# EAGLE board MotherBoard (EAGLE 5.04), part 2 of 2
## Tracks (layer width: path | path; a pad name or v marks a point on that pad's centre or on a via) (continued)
N$125 (continued)
  Bottom 1.016: Q3.3 288.77,206.69 arc90 286.23,204.15 286.23,201.61 arc-90 283.69,199.07 277.34,199.07 arc90 DSP1.6
N$126
  Bottom 1.016: DSP1.8 272.26,212.57 arc-90 274.8,215.11 278.61,215.11 arc-90 281.15,212.57 281.15,207.96 arc-90 Q2.3
N$127
  Bottom 1.016: Q5.3 DSP1.9
N$128
  Bottom 1.016: Q4.3 261.01,211.96 arc-45 DSP1.12
N$129
  Bottom 1.016: R105.1 R102.1 183.36,167.32 arc90 IC11.2
N$130
  Bottom 1.016: D3.C 182.74,157.81 arc-45 D4.A
N$131
  Bottom 1.016: Q1.2 IC6.2
N$132
  Bottom 1.016: Q1.1 149.59,54.29 arc-90 147.8,56.09 IC6.1
N$133
  Bottom 1.016: Q14.2 R122.2 13.18,17.57 arc-90 14.97,19.37 C58.2
N$134
  Bottom 1.016: LED16.A R124.2
N$135
  Bottom 1.016: Q14.3 R124.1
N$136
  Bottom 1.016: LED16.K arc90 14.13,3.81 40.66,3.81 arc90 43.66,6.81 LED17.A
N$137
  Bottom 1.016: R110.1 JP13.1 IC12.2
N$138
  Bottom 1.016: LED3.K R17.1
N$139
  Bottom 1.016: LED5.K R19.1
N$140
  Bottom 1.016: LED6.K R20.1
N$141
  Bottom 0.813: R21.1 LED7.K
N$142
  Bottom 0.813: R22.1 LED8.K
N$143
  Bottom 0.813: R23.1 LED9.K
N$144
  Bottom 0.813: R24.1 LED10.K
N$145
  Bottom 1.016: LED4.K R18.1
N$146
  Bottom 1.016: R99.2 R100.S
N$147
  Bottom 1.016: R106.2 R107.S
N$148
  Bottom 1.016: R99.1 C37.2 JP11.2
N$149
  Bottom 1.016: JP12.2 C39.2 R106.1
N$150
  Bottom 1.016: C70.1 R155.1 R154.2
N$151
  Bottom 1.016: PH1.1 136.37,160.97 R112.1 R111.1
N$152
  Bottom 1.016: 203.04,165.77 S39.2 | S39.1 199.87,165.77 | 199.87,165.77 203.04,165.77 | 203.04,165.77 203.04,165.74 | 199.87,165.77 199.87,167.64 arc90 R104.1
N$153
  Bottom 1.016: 203.04,174.66 S40.2 | S40.1 199.87,174.66 | 199.87,174.66 203.04,174.66 | 203.04,174.66 203.04,174.62 | 199.87,174.66 199.87,176.53 arc90 R108.1
N$154
  Bottom 1.016: S41.1 196.65,183.55 196.69,183.52 196.73,183.55 199.87,183.55 | 199.87,183.55 S41.2 | 199.87,183.55 199.87,186.05 arc90 R109.1
N$155
  Bottom 1.422: C51.1 TR1.3 58.9,4.76 SPK.2
N$156
  Bottom 1.016: S38.1 196.69,156.88 | 196.69,156.88 199.87,156.88 | 199.87,156.88 S38.2 | 196.69,156.88 196.69,156.84 | 199.87,156.88 199.87,158.75 arc90 R103.1
N$157
  Bottom 1.016: R119.1 JP16.2
N$158
  Bottom 1.016: R116.2 R113.1 R115.1
N$159
  Bottom 1.016: TR1.2 R119.2
N$160
  Bottom 1.016: R117.2 117.32,147.75 arc45 C49.1 | R117.2 108.69,136.21 arc-45 D5.A JP15.3 104.12,139.38 arc-90 99.54,143.96 C48.2 | IC13.2 126.84,142.56 arc90 123.67,139.38 arc-90 120.49,136.21 R117.2
N$161
  Top 1.27: IC13.1 126.4,140.02 arc-45 124.98,140.61 123.74,141.85 arc-45 122.4,145.09 R118.A
  Bottom 1.016: R117.1 IC13.1
N$162
  Bottom 1.016: IC8.7 R57.2
N$163
  Bottom 1.016: IC8.6 R58.2
N$164
  Bottom 1.016: IC8.4 R60.2
N$165
  Bottom 1.016: IC8.3 R61.2
N$166
  Bottom 1.016: IC8.2 R62.2
N$167
  Bottom 1.016: IC8.1 R63.2
N$168
  Bottom 1.016: R64.2 IC8.15
N$169
  Bottom 1.016: IC8.5 R59.2
N$170
  Bottom 1.016: R50.2 IC7.6
N$171
  Bottom 1.016: R52.2 IC7.4
N$172
  Bottom 1.016: R53.2 IC7.3
N$173
  Bottom 1.016: R54.2 IC7.2
N$174
  Bottom 1.016: R55.2 IC7.1
N$175
  Bottom 1.27: IC7.15 R56.2
N$176
  Bottom 1.016: R51.2 IC7.5
N$177
  Bottom 1.016: R49.1 291.31,25.96 arc45 290.13,28.8 289.94,28.99 arc-45 288.77,31.83 M1.13
N$178
  Bottom 1.016: R47.2 Q6.2
N$179
  Bottom 1.016: R48.2 Q7.2
N$180
  Bottom 1.016: R65.2 Q8.2
N$181
  Bottom 1.016: R66.2 Q9.2
N$182
  Bottom 1.016: R67.2 Q10.2
N$183
  Bottom 1.016: R68.2 Q11.2
N$184
  Bottom 1.016: R69.2 Q12.2
N$185
  Bottom 1.016: R70.2 Q13.2
N$186
  Bottom 1.778: TR2.1 P2.1
N$187
  Bottom 1.016: LED20.K R136.2
N$188
  Bottom 1.778: P1.1 RE1.1
N$189
  Bottom 1.676: B1.AC1 3.02,203.63 arc-45 SW1.2
N$190
  Bottom 1.016: R140.2 RE1.4 arc90 354.81,50.48 354.81,56.83 arc90 JP19.1
N$191
  Bottom 1.016: JP20.1 325.6,6.56 arc90 327.39,4.76 331.42,4.76 arc90 333.22,6.56 TR2.3
N$192
  Bottom 1.93: 9.45,210.11 11.68,207.87 arc45 13.75,207.01 PWR.+ | 9.45,210.11 PWR.C | SW1.P 5.99,211.77 arc-45 9.04,210.51 9.45,210.11
N$193
  Bottom 1.016: M1.3 R50.1
N$194
  Bottom 1.016: M1.4 R51.1
N$195
  Bottom 1.016: R52.1 M1.10
N$196
  Bottom 1.016: M1.6 R53.1
N$197
  Bottom 1.016: R54.1 M1.11
N$198
  Bottom 1.016: R55.1 M1.15
N$199
  Bottom 1.016: M1.16 281.15,39.94 arc-90 283.44,42.23 R56.1
N$200
  Bottom 1.016: R57.1 M2.13
N$201
  Bottom 1.016: M2.3 253.21,30.91 arc-90 255,32.7 R58.1
N$202
  Bottom 1.016: M2.4 R59.1
N$203
  Bottom 1.016: R60.1 M2.10
N$204
  Bottom 1.016: M2.6 260.83,15.29 arc45 259.29,19 arc-45 258.29,21.43 R61.1
N$205
  Bottom 1.016: R62.1 M2.11
N$206
  Bottom 1.016: R63.1 M2.15
N$207
  Bottom 1.016: R64.1 227.49,38.02 arc-90 232.34,42.86 244.32,42.86 arc-90 M2.16
N$208
  Bottom 1.016: R80.1 R88.2 46.2,180.81 arc45 44.73,184.34 44.24,184.83 arc-45 43.66,186.25 R89.1
N$209
  Bottom 1.016: R81.1 R89.2 43.66,180.81 arc45 42.19,184.34 41.7,184.83 arc-45 41.12,186.25 R90.1
N$210
  Bottom 1.016: R82.1 R90.2 41.12,180.81 arc45 39.65,184.34 39.16,184.83 arc-45 38.58,186.25 R91.1
N$211
  Bottom 1.016: R83.1 R91.2 38.58,180.81 arc45 37.11,184.34 36.62,184.83 arc-45 36.04,186.25 R92.1
N$212
  Bottom 1.016: R84.1 R92.2 36.04,180.81 arc45 34.57,184.34 34.08,184.83 arc-45 33.5,186.25 R93.1
N$213
  Bottom 1.016: R85.1 R93.2 33.5,180.81 arc45 32.03,184.34 31.54,184.83 arc-45 30.96,186.25 R94.1
N$214
  Bottom 1.016: R86.1 R94.2 30.96,180.81 arc45 29.49,184.34 29,184.83 arc-45 28.42,186.25 R95.1
N$215
  Top 1.016: IC10.3 12.12,173.67 arc-90 15.72,170.08 15.72,167.1 arc90 19.31,163.51 21.3,163.51 arc90 25.88,168.09 25.88,173.67 arc-90 R87.1
  Bottom 1.016: R87.1 R95.2 | C35.2 IC10.3
N$216
  Bottom 1.016: S37.1 R80.2
N$217
  Bottom 1.016: S37.2 R81.2
N$218
  Bottom 1.016: S37.3 R82.2
N$219
  Bottom 1.016: S37.4 R83.2
N$220
  Bottom 1.016: S37.5 R84.2
N$221
  Bottom 1.016: S37.6 R85.2
N$222
  Bottom 1.016: S37.7 R86.2
N$223
  Bottom 1.016: S37.8 R87.2
N$224
  Bottom 1.016: LDAC.2 4.29,176.21
  Bottom 1.422: R96.2 arc-45 11.91,179.76 IC10.1 IC10.2 4.29,176.21
N$225
  Bottom 1.016: R97.2 18.78,168.59 arc-90 16.99,170.39 16.99,171.13 | 16.99,171.13 16.99,179.5 arc-90 18.78,181.29 R96.1 | 16.99,171.13 IC10.5
N$226
  Bottom 1.016: IC10.6 LED15.K 23.34,169.23 arc-90 R98.2
N$227
  Bottom 1.016: IC10.7 LED15.A
N$228
  Bottom 1.27: 58.87,213.04 58.87,213.02 58.37,212.52 arc45 57.63,210.72 IC9.6 | 58.87,213.04 RS485.2 | 58.87,213.04 R71.2
N$229
  Top 0.406: 169.39,175.58 169.39,176.21 166.85,176.21 166.85,175.58
N$230
  Bottom 0.61: JP10.1 | LED12.A
  Bottom 1.016: LED11.A 66.2,182.56 | 66.2,182.56 LED12.A 66.04,187.64 | 66.2,182.56 LED13.A | 66.04,187.64 JP10.1 | 66.04,187.64 LED14.A
N$231
  Bottom 1.422: PDAC.1 arc90 6.85,147 C71.1 R155.2
N$232
  Bottom 1.016: R154.1 19,147 arc90 20.8,148.8 JP25.2
N$233
  Bottom 1.016: 56.36,202.88 IC9.2 | 56.36,202.88 IC9.3 | S36.3 56.36,202.88
N$234
  Bottom 1.016: S36.2 58.9,199.82 arc-45 59.27,200.71 59.79,201.24 arc45 60.17,202.14 IC9.4
N$235
  Bottom 1.016: S36.4 53.82,199.82 arc45 53.44,200.71 52.92,201.24 arc-45 52.55,202.14 IC9.1
N$236
  Bottom 1.016: C45.2 R114.E
N$237
  Top 0.406: 156.69,175.58 156.69,176.21 159.23,176.21 159.23,175.58
N$238
  Bottom 1.016: R143.2 127.48,35.99 arc90 125.68,37.78 R145.2 arc45 124.3,36.25 Q15.1
N$239
  Bottom 1.016: R141.2 LED21.K
N$240
  Bottom 1.016: R141.1 123.67,31.43 | 123.67,31.43 D6.A arc-90 121.76,32.7 Q15.2 | Q15.2 | 123.67,31.43 K1.16
N$241
  Bottom 1.016: 117.32,6.03 QR1.2
  Bottom 2.184: K1.S1 116.05,9.1 arc45 117.32,6.03
  Bottom 2.54: 117.32,6.03 117.34,6.01
N$242
  Bottom 1.016: R144.2 142.72,35.99 arc90 140.92,37.78 R146.2 140.13,37.74 arc45 139.54,36.32 Q16.1
N$243
  Bottom 1.016: R142.2 LED22.K
N$244
  Bottom 1.016: 138.91,31.43 D7.A arc-90 137,32.7 Q16.2 | 138.91,31.43 R142.1 | 138.91,31.43 K2.16
N$245
  Bottom 1.016: 132.58,6.01 132.56,6.03 QR2.2
  Bottom 2.54: K2.S1 131.29,9.1 arc45 132.56,6.03
N$246
  Bottom 1.016: Q18.2 75.56,26.35 arc-90 72.87,29.05 R153.1 72.87,31.82 arc-90 76.29,35.24 OK2.5
N$247
  Bottom 1.676: Q17.1 89.53,26.35 arc-90 86.84,29.05 R157.2 86.84,32.7 R158.2
N$248
  Bottom 1.016: OK2.1 R156.2
N$249
  Bottom 1.016: 84.3,7.3 M.1 | 86.84,23.81 85.32,23.81 arc-90 83.03,26.1 LED23.K
  Bottom 1.676: Q17.2 86.84,23.81 D10.C | 84.3,7.3 84.3,10.59 arc-45 C69.1 arc45 86.84,16.72 D10.C | D10.C D9.A
N$250
  Bottom 1.016: LED23.A 80.49,24.45 arc90 R151.1
N$251
  Bottom 1.016: R152.1 OK2.6
N$252
  Bottom 1.016: Q18.3 R157.1 77.65,30.16 arc90 80.49,33 R159.2
N$253
  Bottom 1.016: 220V.1 R147.1
N$254
  Bottom 1.016: QR1.1 122.4,6.67 122.37,6.06 QR1.1
  Bottom 2.184: K1.P2 120.02,21.27 | 120.02,21.27 K1.P1 | 120.02,21.27 120.02,10.99 arc45 120.94,8.76 121.84,7.85 arc-45 122.37,6.58 122.37,6.06
N$255
  Bottom 1.016: R148.1 C66.1 R147.2
N$256
  Bottom 1.016: 137.61,7.33 137.64,6.67
  Bottom 2.184: K2.P2 135.26,21.27 | 135.26,21.27 K2.P1 | 135.26,21.27 135.26,11.14 arc45 136.28,8.65 137.61,7.33 | 137.64,6.67 QR2.1
N$257
  Bottom 1.016: 217.65,14.92 R148.2 217.65,9.84 | 217.65,14.92 217.65,17.46 arc90 Z4.A | 217.65,9.84 C66.2 | D8.A 217.65,9.84 | 217.65,14.92 P3.1
N$258
  Bottom 1.016: Z6.A R150.1 Z5.A arc45 210.77,10.59 209.28,9.1 arc45 207.49,4.76 | P5.1 207.49,4.76 | 207.49,4.76 220V.2
N$259
  Bottom 1.016: OK1.3 R150.2
N$260
  Bottom 1.016: OK1.2 Z5.C | Z5.C D8.C | Z5.C arc90 210.03,17.46 P4.1
N$261
  Top 0.406: 22.86,153.35 23.65,153.35 23.65,150.81 22.86,150.81
N$262
  Bottom 1.016: Z6.C Z4.C
N$263
  Top 0.406: 53.82,35.88 53.82,35.24 56.36,35.24 56.36,35.88
N$264
  Top 0.61: 98.9,138.75 100.81,140.65 | 100.81,140.65 100.17,140.65 | 100.81,140.65 100.81,140.02
N$265
  Bottom 0.61: 130.65,207.96 LPT.4
  Bottom 1.016: R7.1 130.65,207.96
N$266
  Bottom 1.016: LPT.5 133.51,207.96 R8.1
N$267
  Top 0.406: 50.64,25.08 50.01,25.08 50.01,22.54 50.64,22.54
N$268
  Top 0.406: 22.7,20 22.07,20 22.07,17.46 22.7,17.46
N$269
  Bottom 1.016: LED12.K R26.2
N$270
  Bottom 1.016: LED13.K R27.2
N$271
  Bottom 1.016: LED14.K R28.2
N$272  (via drill 0.6 pad 1.68)
  Top 1.016: v258.29,72.07 v258.29,66.99
  Bottom 1.016: S35.1 198.6,68.48 arc-90 202.19,72.07 v258.29,72.07 | v258.29,66.99 R47.1
N$273
  Bottom 1.016: S35.8 248.13,66.99 arc-90 R70.1
N$274
  Bottom 1.016: R69.1 215.63,64.45 arc-90 213.84,66.25 S35.7
N$275
  Bottom 1.016: S35.2 201.14,67.74 arc-90 202.93,69.53 276.07,69.53 arc-90 R48.1
N$276
  Bottom 1.016: JP7.1 R17.2 R18.2 R19.2 R20.2
N$277
  Bottom 0.813: R21.2 R22.2 R23.2 R24.2
  Bottom 1.016: R21.2 JP9.1
N$278
  Bottom 1.016: LPT.6 136.05,207.96 R9.1
N$279
  Bottom 1.016: R10.1 LPT.7
N$280
  Bottom 1.016: LPT.8 141.76,207.96 R11.1
N$281
  Bottom 1.016: LPT.9 144.3,207.96 R13.1
N$282
  Bottom 1.016: LPT.10 147.16,207.96 R15.1
N$283
  Bottom 1.016: R65.1 296.39,62.81 arc-90 287.87,54.29 216.38,54.29 arc-90 S35.3
N$284
  Bottom 1.016: R68.1 arc-90 263.37,61.91 215.88,61.91 arc-90 211.3,66.49 S35.6
N$285
  Bottom 1.016: S35.5 arc90 216.38,59.37 268.95,59.37 arc90 273.53,63.95 R67.1
N$286
  Bottom 1.016: S35.4 arc90 216.38,56.83 281.93,56.83 arc90 288.77,63.67 R66.1
N$287
  Top 0.406: 55.09,170.5 55.09,171.13 52.55,171.13 52.55,170.5
N$288
  Top 0.406: 17.62,24.45 16.99,24.45 16.99,21.91 17.62,21.91
N$289
  Top 0.406: 68.1,191.77 68.74,191.77 68.74,189.23 68.1,189.23
N$290
  Top 0.406: 138.27,45.4 137.64,45.4 137.64,42.86 138.27,42.86
N$291
  Top 0.406: 123.03,45.4 122.4,45.4 122.4,42.86 123.03,42.86
N$292
  Top 0.406: 221.14,1.91 arc-203 223.04,1.91 arc203 224.95,1.91
N$293
  Top 0.406: 213.84,171.77 213.84,172.4 216.38,172.4 216.38,171.77
N$294
  Top 0.406: 210.03,28.89 210.03,28.26 212.57,28.26 212.57,28.89
N$295
  Top 0.406: 330.68,64.45 330.04,64.45 330.04,66.99 330.68,66.99
N$296
  Top 0.406: 323.06,10.48 322.42,10.48 322.42,7.3 323.06,7.3
N$297
  Top 0.406: 351,60.64 351,61.28 353.54,61.28 353.54,60.64
NTC
  Bottom 1.016: S42.15 154.15,165.53 arc90 152.35,167.32 128.26,167.32 arc45 122.58,164.97 C46.2 R115.2
ON-GLCD
  Bottom 1.016: 324.96,112.71 SW3.P | GLCD.2 282.89,122.12 282.89,120.09 arc90 286.46,116.52 307.19,116.52 arc-45 310.43,115.18 311.04,114.57 arc45 315.53,112.71 324.96,112.71 | GLCD.19 239.76,119.46 arc91 243.85,115.37 268.59,115.39 arc-45 274.31,113.03 277.54,109.8 arc55 284.32,107 318.61,107 arc90 324.96,112.71
ON-LCD
  Bottom 1.016: 232.88,103.85 arc1 232.88,102.54 232.88,100.89 arc90 234.24,99.54 264.55,99.54 arc90 265.91,100.89 LCD.15 | 232.88,103.85 LCD.2 | 232.88,103.85 232.88,104.2 arc45 231.35,107.9 R29.A 223.78,115.25 arc90 220.19,111.66 220.19,109.95 arc-90 216.59,106.36 SW2.P
P2  (via drill 0.6 pad 1.68)
  Top 1.016: v81.76,133.67 81.76,180.52 arc-90 86.34,185.1 R26.1
  Bottom 0.61: R26.1 87.36,185.1 arc-45 88.63,184.58 arc45 90.43,183.83 91.82,183.83 arc-45 93.64,183.08 95.04,181.68 arc-45 S31.7
  Bottom 1.016: 46.2,133.67 PORTE.1 S2.8 | 46.2,133.67 v81.76,133.67 U1.2 | S31.7 95.73,179.06 arc-90 90.34,173.67 62.97,173.67 arc-90 53.82,182.83 S36.5 | 46.2,133.67 S37.16
P3  (via drill 0.6 pad 1.68)
  Top 1.016: v86.84,131.13 R25.1 | v43.66,131.13 v43.66,136.21
  Bottom 1.016: S31.5 R25.1 85.47,178.66 arc-45 82.63,177.48 67.03,177.48 arc-90 58.9,185.61 S36.7 | U1.3 v86.84,131.13 v43.66,131.13 PORTE.2 S2.7 | v43.66,136.21 S37.15
P4  (via drill 0.6 pad 1.68)
  Top 1.016: v84.3,128.59 84.3,180.77 arc-90 86.09,182.56 R27.1 | v41.12,128.59 v41.12,136.21
  Bottom 0.61: R27.1 90.74,182.56 arc-45 92.75,181.73 92.81,181.66 arc-45 93.19,180.77 S31.6
  Bottom 1.016: U1.4 v84.3,128.59 v41.12,128.59 PORTE.3 S2.6 | S31.6 93.19,179.64 arc-90 89.12,175.58 65.18,175.58 arc-90 56.36,184.4 S36.6 | v41.12,136.21 S37.14
P5  (via drill 0.6 pad 1.68)
  Top 1.016: v79.22,126.05 79.22,180.46 arc-90 86.4,187.64 R28.1 | v38.58,136.21 v38.58,126.05
  Bottom 0.61: R28.1 arc-45 87.92,187.19 89.08,186.03 arc45 91.33,185.1 93.46,185.1 arc-45 95.54,184.24 97.21,182.56 arc-45 S31.8
  Bottom 1.016: v79.22,126.05 U1.5 | S2.5 PORTE.4 v38.58,126.05 v79.22,126.05 | v79.22,126.05 79.22,125.89 | v38.58,136.21 S37.13 38.58,157.5 arc90 35.74,160.34 25.8,160.34 arc90 20.8,155.34 JP25.1
P6  (via drill 0.6 pad 1.68)
  Top 1.016: v76.68,123.51 76.68,156.88 arc90 S7.1 | v36.04,136.21 v36.04,123.51
  Bottom 1.016: U1.6 v76.68,123.51 v36.04,123.51 PORTE.5 S2.4 | S7.1 67.19,159.98 67.15,160.02 | 67.15,160.02 67.11,159.98 S7.2 | 67.15,160.02 arc45 64.85,160.97 LED3.A | v36.04,136.21 S37.12
P7  (via drill 0.6 pad 1.68)
  Top 1.016: v69.37,120.97 69.37,150.06 arc90 S8.2 | v33.5,136.21 v33.5,120.97
  Bottom 1.016: U1.7 v69.37,120.97 v33.5,120.97 PORTE.6 S2.3 | S8.1 67.19,152.36 67.15,152.4 | 67.15,152.4 67.11,152.36 S8.2 | 67.15,152.4 arc45 64.85,153.35 LED4.A | v33.5,136.21 S37.11
P8  (via drill 0.6 pad 1.68)
  Top 1.016: v71.28,118.43 71.28,142.52 arc-90 73.5,144.74 S13.1 | v30.96,136.21 v30.96,118.43
  Bottom 1.016: U1.8 v71.28,118.43 v30.96,118.43 PORTE.7 S2.2 | S13.1 67.19,144.74 67.15,144.78 | 67.15,144.78 67.11,144.74 S13.2 | 67.15,144.78 arc45 64.85,145.73 LED5.A | v30.96,136.21 S37.10
P9  (via drill 0.6 pad 1.68)
  Top 1.016: S14.2 67.15,137.12 v67.15,115.89 | v28.42,136.21 v28.42,115.89
  Bottom 1.016: U1.9 v67.15,115.89 v28.42,115.89 PORTE.8 S2.1 | S14.1 67.19,137.12 67.15,137.16 | 67.15,137.16 67.11,137.12 S14.2 | 67.15,137.16 arc45 64.85,138.11 LED6.A | v28.42,136.21 S37.9
P10  (via drill 0.6 pad 1.68)
  Top 1.016: v56.36,113.35 56.36,90.97 arc-92 S9.3
  Bottom 1.016: U1.10 v56.36,113.35 42.01,113.35 arc90 23.34,94.67 23.34,91.76 arc-90 PORTB.1 S4.8 | S43.5 41.12,67.36 arc-45 42.65,71.07 43.7,72.12 arc45 46.2,78.14 46.2,82.76 arc-90 50.8,87.36 S9.3
P11  (via drill 0.6 pad 1.68)
  Top 1.016: v91.92,110.81 91.92,162.9 arc-45 94.15,168.28 102.38,176.52 arc45 103.98,180.38 103.98,186.18 arc-45 104.57,187.6 R16.2 | S10.3 70.87,87.36 arc90 75.41,91.9 v75.41,110.81
  Bottom 1.016: R16.2 C14.2 | U1.11 v91.92,110.81 v75.41,110.81 42.15,110.81 arc90 25.88,94.53 25.88,89.6 arc-90 23.59,87.31 PORTB.2 S4.7 14.97,87.31 arc90 13.18,85.52 13.18,71.44 arc90 16.35,68.26 21.49,68.26 arc-45 25.73,66.51 31.11,61.12 arc45 33.8,60.01 arc90 36.04,62.24 S43.7
P12  (via drill 0.6 pad 1.68)
  Top 1.016: R12.2 arc63 106.59,177.62 arc-18 104.78,175.1 96.12,166.45 arc45 94.46,162.43 v94.46,108.27 94.46,93.61 arc-90 S11.3
  Bottom 1.016: S4.6 PORTB.3 25.24,84.77 arc90 28.42,87.95 28.42,93.17 arc-90 43.51,108.27 v94.46,108.27 U1.12 | R12.2 C13.2 | S43.6 38.58,69.14 arc-45 39.75,71.98 41.3,73.53 arc45 43.66,79.21 43.66,84.17 arc-90 49.34,89.85 83.99,89.85 arc-45 86.68,88.74 88.11,87.31 88.16,87.36 S11.3
P13  (via drill 0.6 pad 1.68)
  Top 1.016: R14.2 arc45 102.08,193.47 102.08,181.92 arc-45 100.74,178.68 91.27,169.22 arc45 89.38,164.64 v89.38,105.73 | S12.3 106.88,87.36 arc90 112.24,92.72 v112.24,105.73 | v27.15,82.23 v27.15,69.53
  Bottom 1.016: S4.5 PORTB.4 v27.15,82.23 arc90 30.96,86.04 30.96,91.8 arc-90 44.88,105.73 v89.38,105.73 v112.24,105.73 U1.13 | v27.15,69.53 arc-90 S43.8
P14  (via drill 0.6 pad 1.68)
  Top 1.016: v52.55,103.19 52.55,92.44 S9.1 52.6,92.34 52.55,92.39 arc90 48.74,88.58 v48.74,80.96
  Bottom 1.016: S4.4 PORTB.5 28.11,79.69 arc90 33.5,85.08 33.5,89.79 arc-90 46.89,103.19 v52.55,103.19 U1.14 | JP16.1 arc-45 50.38,25.98 49.14,27.22 arc-45 46.2,34.32 46.2,64.14 arc-45 47.31,66.84 47.62,67.15 arc45 48.74,69.84 v48.74,80.96
P15  (via drill 0.6 pad 1.68)
  Top 1.016: v59.06,100.65 59.06,89.53 arc-45 55.66,81.37 S15.1 52.6,78.37 52.55,78.42 47.28,73.16 arc45 44.93,67.48 44.93,29.41 arc-90 39.97,24.45 v22.07,24.45
  Bottom 1.016: S4.3 PORTB.6 28.63,77.15 arc90 36.04,84.56 36.04,87.87 arc-90 48.82,100.65 v59.06,100.65 U1.15 | v22.07,24.45 JP17.1
P16  (via drill 0.6 pad 1.68)
  Top 1.016: v61.75,98.11 61.75,81.9 arc-45 55.87,67.63 S20.1
  Bottom 1.016: S4.2 PORTB.7 29.42,74.61 arc90 38.58,83.77 38.58,86.8 arc-90 49.88,98.11 v61.75,98.11 U1.16 | S20.1 52.55,64.4 52.55,64.45 51.58,64.45 arc90 48.74,61.61 48.74,41.59 arc90 52.55,37.78 JP24.1
P17  (via drill 0.6 pad 1.68)
  Top 1.016: v78.58,95.41 78.58,71.04 arc-45 76.37,65.69 73.74,63.07 arc-45 70.96,61.91 64.18,61.91 arc45 61.29,60.71 53.81,53.23 arc45 S25.1 52.6,50.43 52.55,50.48 49,46.94 arc45 47.47,43.23 47.47,28.13 arc-90 39.33,20 v27.15,20
  Bottom 1.016: S4.1 PORTB.8 30.19,72.07 arc90 41.12,83 41.12,85.98 arc-90 50.55,95.41 v78.58,95.41 137.53,95.41 arc-45 142.32,93.43 U1.17 | v27.15,20 JP18.2
P25  (via drill 0.6 pad 1.68)
  Top 1.016: v164.31,79.69 177.75,79.69 arc45 185.15,82.76 210.12,107.73 arc45 211.3,110.57 211.3,111.03 arc-45 212.06,112.88 216.16,116.98 arc-45 221.19,119.06 225.12,119.06 arc45 229.7,120.96 237.52,128.77 arc45 243.05,142.12 243.05,208.52 arc45 239.85,216.24 R126.1 | S19.1 164.31,37.5 v164.31,37.46
  Bottom 0.813: S19.1 192.84,37.5 192.88,37.46 192.92,37.5 S19.2 arc-24 197,36.66 LED7.A
  Bottom 1.016: PORTD.1 S6.8 PORTD.1 | PORTD.1 v164.31,37.46 v164.31,79.69 | v164.31,79.69 U1.25 | R126.1 238.74,217.35 arc45 234.84,218.96 PS2.5 | v164.31,79.69 S33.8
P26  (via drill 0.6 pad 1.68)
  Top 1.016: S24.1 166.85,45.12 v166.85,45.08 | v166.85,77.15 S33.7
  Bottom 0.813: S24.1 S24.2 | S24.2 193.16,45.12 193.2,45.08 | S24.2 arc-24 197,44.28 LED8.A
  Bottom 1.016: PORTD.2 S6.7 PORTD.2 | PORTD.2 v166.85,45.08 v166.85,77.15 U1.26
P27  (via drill 0.6 pad 1.68)
  Top 1.016: v169.39,82.23 175.83,82.23 arc45 184.35,85.76 205.25,106.66 arc45 208.76,115.14 208.76,167.51 arc-45 210.42,171.53 v216.38,177.48 | S29.1 169.39,52.74 v169.39,52.71 | v169.39,74.61 S33.6
  Bottom 0.813: 192.88,52.74 S29.2 arc-24 197,51.9 LED9.A | S29.1 192.88,52.74 | 192.88,52.74 192.88,52.71
  Bottom 1.016: PORTD.3 S6.6 PORTD.3 | PORTD.3 v169.39,52.71 v169.39,74.61 v169.39,82.23 U1.27 | v216.38,177.48 S32.7
P28  (via drill 0.6 pad 1.68)
  Top 1.016: v171.93,84.77 174.84,84.77 arc45 182.97,88.14 202.88,108.05 arc45 206.22,116.1 206.22,170.05 arc-45 207.88,174.07 v211.3,177.48 | v171.93,72.07 S33.5 | S30.1 186.49,60.36 186.53,60.33 v171.93,60.33
  Bottom 0.813: S30.1 186.53,60.36 | 186.53,60.36 S30.2 194.45,60.36 arc-38 LED10.A | 186.53,60.36 186.53,60.33
  Bottom 1.016: PORTD.4 S6.5 PORTD.4 | PORTD.4 v171.93,60.33 v171.93,72.07 v171.93,84.77 U1.28 | v211.3,177.48 S32.5
P29
  Bottom 1.016: S6.4 PORTD.5 | PORTD.5 U1.29 | S6.4 PORTD.5 | JP23.1 185.82,12.38 arc-45 183.79,13.22 arc45 182.75,13.65 179.33,13.65 arc-90 174.47,18.51 S6.4
P30  (via drill 0.6 pad 1.68)
  Top 1.016: v135.1,47.94 v177.01,47.94
  Bottom 1.016: PORTD.6 S6.3 PORTD.6 | PORTD.6 v177.01,47.94 U1.30 | JP21.1 arc-90 127.48,47.94 v135.1,47.94
P31
  Bottom 1.016: S6.2 PORTD.7 | PORTD.7 U1.31 | S6.2 PORTD.7 | JP23.3 185.25,17.46 arc45 184.19,17.02 183.77,16.61 arc-45 182.77,16.19 182.09,16.19 arc-90 S6.2
P32  (via drill 0.6 pad 1.68)
  Top 1.016: v161.77,56.83 v182.09,56.83
  Bottom 1.016: PORTD.8 S6.1 PORTD.8 | PORTD.8 v182.09,56.83 U1.32 | JP22.1 158.17,45.4 arc90 161.77,48.99 v161.77,56.83
P33
  Bottom 1.016: IC8.11 IC8.12 227.81,30.16 arc90 225.27,27.62 | 319.25,9.84 319.25,22.02 arc90 317.45,23.81 IC7.11 IC7.12 | 319.25,9.84 JP20.2 | U1.33 arc-90 189.71,96.84 189.71,79.47 arc22 190.88,73.59 191.39,72.34 arc22 195.33,66.45 199.79,61.99 arc-45 203.68,52.61 203.68,30.16 arc90 206.22,27.62 225.27,27.62 | 225.27,27.62 225.27,21.27 arc90 229.08,17.46 arc-45 235.58,14.77 240.67,9.68 | 240.67,9.68 arc0 240.67,9.68 | 240.67,9.68 arc45 247.18,6.98 316.39,6.98 arc90 319.25,9.84
P34
  Bottom 1.016: 324.33,53.02 324.33,36.82 arc-90 318.94,31.43 IC7.14 | U1.34 189.71,100.65 arc-90 192.25,98.11 192.25,81.73 arc90 196.83,77.15 320.31,77.15 arc-90 324.33,73.14 324.33,53.02 | 324.33,53.02 346.42,53.02 arc90 351,57.6 JP19.2
P35  (via drill 0.6 pad 1.68)
  Top 1.016: S35.16 v198.6,79.69
  Bottom 1.016: S3.8 PORTC.1 333.22,79.69 | U1.35 190.98,103.19 arc-90 194.79,99.38 194.79,83.5 arc90 v198.6,79.69 333.22,79.69 | 333.22,79.69 JP13.2
P36  (via drill 0.6 pad 1.68)
  Top 1.016: v201.14,82.23 S35.15
  Bottom 1.016: S3.7 PORTC.2 v201.14,82.23 arc-90 197.33,86.04 197.33,101.92 arc90 193.52,105.73 U1.36
P37  (via drill 0.6 pad 1.68)
  Top 1.016: GLCD.16 247.38,113.88 arc-45 244.22,106.27 arc45 243.05,103.43 LCD.6 v243.05,84.77 | v203.68,84.77 S35.14
  Bottom 1.016: S3.6 PORTC.3 v243.05,84.77 v203.68,84.77 arc-90 199.87,88.58 199.87,104.46 arc90 196.06,108.27 U1.37
P38  (via drill 0.6 pad 1.68)
  Top 1.016: GLCD.17 244.84,117.5 arc-45 240.92,108.05 238.8,105.92 arc45 237.97,103.92 LCD.4 v237.97,87.31 | v206.22,87.31 S35.13
  Bottom 1.016: S3.5 PORTC.4 v237.97,87.31 v206.22,87.31 arc-90 202.41,91.12 202.41,107 arc90 198.6,110.81 U1.38
P39  (via drill 0.6 pad 1.68)
  Top 1.016: v255.75,89.85 v255.74,89.86 LCD.11 LCD.11 arc45 253.95,106.89 251.85,108.99 arc-45 249.92,113.65 GLCD.15 249.92,122.73 arc45 248.39,126.42 arc-45 246.86,130.12 246.86,150.03 arc-45 249.21,155.71 249.77,156.26 arc45 251.94,161.5 251.94,186.87 arc-90 256.52,191.45 272.9,191.45 arc45 276.14,192.79 277.87,194.53 arc-45 282.71,196.53 S34.5 | v208.76,89.85 S35.12
  Bottom 1.016: S3.4 PORTC.5 v255.75,89.85 v208.76,89.85 arc-90 204.95,93.66 204.95,109.54 arc90 201.14,113.35 U1.39 | LCD.11
P40  (via drill 0.6 pad 1.68)
  Top 1.016: LCD.12 v258.29,92.39 | LCD.12 | LCD.12 258.29,103.92 arc-45 259.12,105.92 271.49,118.3 arc45 272.78,121.4 GLCD.6 272.78,145.1 arc-45 275.39,151.4 293.05,169.06 arc45 298.93,183.26 S34.6 | v211.3,92.39 S35.11
  Bottom 1.016: S3.3 PORTC.6 v258.29,92.39 v211.3,92.39 arc-90 207.49,96.2 207.49,112.08 arc90 203.68,115.89 U1.40
P41  (via drill 0.6 pad 1.68)
  Top 1.016: LCD.13 v260.83,94.93 | LCD.13 | LCD.13 260.83,103.43 arc-45 262,106.27 273.66,117.93 arc45 275.32,121.92 GLCD.5 275.32,143.33 arc-45 278.28,150.48 295.33,167.54 arc45 301.47,182.35 S34.7 | v213.84,94.93 S35.10
  Bottom 1.016: S3.2 PORTC.7 v260.83,94.93 v213.84,94.93 arc-90 210.03,98.74 210.03,114.62 arc90 206.22,118.43 U1.41
P42  (via drill 0.6 pad 1.68)
  Top 1.016: LCD.14 v263.37,97.47 | LCD.14 | LCD.14 263.37,102.74 arc-45 265.03,106.76 276.57,118.3 arc45 277.86,121.4 GLCD.4 277.86,141.88 arc-45 280.95,149.35 298.34,166.74 arc45 304.01,180.42 S34.8 | v216.38,97.47 S35.9
  Bottom 1.016: S3.1 PORTC.8 v263.37,97.47 v216.38,97.47 arc-90 212.57,101.28 212.57,117.16 arc90 208.76,120.97 U1.42
P43  (via drill 0.6 pad 1.68)
  Top 1.016: 221.77,169.86 v221.77,123.51 | R127.1 221.77,169.86 | 221.77,169.86 JP14.2
  Bottom 0.813: PS2.1 231.65,216.36 arc-45 231.12,215.09 arc-45 229.25,214.31 227.81,214.31
  Bottom 1.016: R127.1 arc-45 222.9,209.4 227.81,214.31 | v221.77,123.51 U1.43
P44  (via drill 0.6 pad 1.68)
  Top 1.016: GLCD.14 252.41,122.12 v252.41,126.05 251.76,126.7 arc-45 249.4,132.41 249.4,148.25 arc-45 252.1,154.79 252.47,155.16 arc45 254.48,160 254.48,184.8 arc-90 257.32,187.64 268.45,187.64 arc-90 R45.1
  Bottom 1.016: U1.44 v252.41,126.05 PORTA.1 S5.8
P45  (via drill 0.6 pad 1.68)
  Top 1.016: GLCD.13 254.95,122.12 v254.95,128.59 254.95,146.32 arc-45 257.57,152.64 257.7,152.76 arc45 259.56,157.25 R44.1
  Bottom 1.016: U1.45 v254.95,128.59 PORTA.2 S5.7
P46  (via drill 0.6 pad 1.68)
  Top 1.016: GLCD.12 257.49,122.12 v257.49,131.13 257.49,145.54 arc-45 259.76,151.02 259.93,151.18 arc45 262.1,156.42 R43.1
  Bottom 1.016: U1.46 v257.49,131.13 PORTA.3 S5.6
P47  (via drill 0.6 pad 1.68)
  Top 1.016: GLCD.11 260.03,122.12 v260.03,133.67 260.03,144.94 arc-45 261.83,149.27 262.25,149.7 arc45 264.64,155.45 R42.1
  Bottom 1.016: U1.47 v260.03,133.67 R138.2 PORTA.4 S5.5
P48  (via drill 0.6 pad 1.68)
  Top 1.016: GLCD.10 262.57,122.12 v262.57,136.21 262.57,143.2 arc-45 264.7,148.34 266.88,150.52 arc45 269.72,157.36 R41.1
  Bottom 1.016: U1.48 v262.57,136.21 R137.2 PORTA.5 S5.4
P49  (via drill 0.6 pad 1.68)
  Top 1.016: GLCD.9 265.11,122.12 v265.11,138.75 265.11,142.9 arc-45 266.55,146.38 273.81,153.63 arc45 277.34,162.15 R40.1
  Bottom 1.016: U1.49 182.09,142.32 arc45 183.26,139.48 arc45 185.02,138.75 v265.11,138.75 R139.2 PORTA.6 S5.3
P50  (via drill 0.6 pad 1.68)
  Top 1.016: GLCD.8 267.65,122.12 v267.65,141.29 | R39.1 257.02,158.52 arc-45 255.16,154.03 arc45 251.94,146.26 v251.94,141.29
  Bottom 1.016: U1.50 179.55,143.19 arc-90 182.09,145.73 182.73,145.73 arc-45 185.97,144.39 187.66,142.7 arc45 191.07,141.29 v251.94,141.29 v267.65,141.29 PORTA.7 S5.2 | S32.8 250.14,180.02 arc45 255.38,182.19 R39.1
P51  (via drill 0.6 pad 1.68)
  Top 1.016: GLCD.7 270.19,122.12 v270.19,143.83
  Bottom 1.016: v270.19,143.83 PORTA.8 S5.1 | v270.19,143.83 208.76,143.83 | 208.76,143.83 193.15,143.83 arc-45 190.53,144.91 189.55,145.89 arc45 183.8,148.27 181.59,148.27 arc90 177.01,143.69 U1.51 | v270.19,143.83 270.19,161.07 arc45 268.8,164.43 268.52,164.71 arc-45 267.18,167.95 R46.1 | 208.76,143.83 208.76,169.77 arc-45 210.62,174.26 212.78,176.43 arc45 213.84,178.97 S32.6
P54
  Bottom 1.016: U1.54 PORTF.1 S42.8
P55
  Bottom 1.016: U1.55 PORTF.2 S42.7
P56
  Bottom 1.016: U1.56 PORTF.3 S42.6
P57
  Bottom 1.016: U1.57 PORTF.4 S42.5
P58
  Bottom 1.016: U1.58 PORTF.5 S42.4
P59
  Bottom 1.016: U1.59 PORTF.6 S42.3
P60
  Bottom 1.016: U1.60 PORTF.7 S42.2
P61
  Bottom 1.016: U1.61 PORTF.8 S42.1
P62  (via drill 0.6 pad 1.52)
  Top 1.016: v149.07,147 146.83,147 arc45 139.81,144.1 130.75,135.04 arc-45 125.91,133.03 107.46,133.03 arc-90 102.08,138.42 C47.2
  Bottom 1.016: C47.2 102.08,143.72 arc90 103.87,141.92 JP15.2 | v149.07,147 U1.62
PE
  Top 1.016: R159.1 85.47,35.24 arc45 83.46,34.41 82.5,33.45 arc-45 80.7,32.7 OK2.4
  Bottom 1.016: 100.81,7.3 POW.1
  Bottom 1.676: 94.46,21.27 97,21.27 | 94.46,21.27 Q17.3 | 97,21.27 arc-90 100.81,17.46 JP27.2 100.81,7.3 | 97,21.27 D10.A | 94.46,21.27 R158.1 R159.1 R152.2
PG1
  Bottom 0.61: LPT.2 124.94,207.96 124.94,206.25 arc90 129.25,201.93 148.56,201.93 arc90 152.88,206.25 152.88,207.96 LPT.12
PG3
  Bottom 0.61: LPT.3 127.79,207.96 127.79,205.74 arc90 130.33,203.2 147.48,203.2 arc90 150.02,205.74 150.02,207.96 LPT.11
PG5
  Bottom 1.016: R3.1 110.07,191.08 arc45 IC2.16
PG10
  Bottom 0.61: IC2.9 142.08,200.34 arc-90 R15.2
PG11
  Bottom 0.406: 117.32,199.07 122.4,199.07
  Bottom 0.61: 122.4,199.07 140.49,199.07 arc-90 R13.2
  Bottom 1.016: IC2.17 112.98,187.64 arc90 114.78,189.44 114.78,192.72 | 114.78,192.72 114.78,197.8 | 114.78,197.8 IC2.13 | 114.78,192.72 IC2.15 | 114.78,197.8 arc-90 116.05,199.07 117.32,199.07
PG12
  Bottom 0.406: 117.32,183.83 122.4,183.83
  Bottom 0.61: 116.05,182.56 117.32,183.83
  Bottom 1.016: R7.2 R6.1 128.25,192.72 arc90 123.67,188.14 123.67,185.1 arc-90 122.4,183.83 | IC2.19 116.05,182.56
PG13
  Bottom 1.016: R8.2 R5.1 arc-90 131.45,190.66 128.2,190.66 arc90 125.73,188.19 125.73,184.36 arc-90 121.4,180.02 IC2.1
PG14
  Bottom 0.813: 122.4,197.8 IC2.8 | 122.4,197.8 134.46,197.8 arc-90 136.05,196.21 R9.2 | IC2.6 120.6,192.72 arc90 122.4,194.52 122.4,197.8
PG15
  Top 1.016: IC2.2 121.14,182.56 arc45 131.96,187.04 138.01,193.09 arc45 R10.2
PG16
  Top 1.016: R11.2 arc90 137.95,199.07 132.65,199.07 arc45 128.16,197.21 126.6,195.66 arc45 124.94,191.64 arc-90 120.94,187.64 IC2.4
PG17
  Bottom 1.016: R12.1 108.43,186.9 arc90 110.22,185.1 IC2.18
PG18
  Bottom 1.016: R14.1 C12.2 R4.1 111.18,204.86 arc-56 IC2.11
PG19
  Bottom 1.016: 109.7,199.07 arc-90 110.97,200.34 IC2.12 | 109.7,199.07 109.7,197.06 arc90 111.49,195.26 IC2.14 | R16.1 109.7,199.07
PRE_S
  Top 1.27: PS1.4 146.53,174.42 arc-90 148.32,176.21 R120.2
  Bottom 1.016: C54.2 arc90 150.34,177.48 R120.2 150.34,174.07 arc45 152.78,169.96 155.31,168.34 arc-57 S42.14
PULS
  Bottom 1.016: JP23.2 C67.2 | C67.2 OK1.6 | C67.2 R149.1
PWM
  Bottom 1.016: R156.1 JP24.2
QH
  Bottom 1.016: IC8.14 231.32,25.08 arc-90 234.16,22.24 arc45 236.05,17.66 242.17,11.55 arc45 248.59,8.89 313.99,8.89 arc90 316.71,11.6 IC7.9
RS232A1
  Bottom 0.61: 77.63,207.96 COM1.2
  Bottom 1.016: IC3.14 77.95,207.64 77.63,207.96
RS232A2  (via drill 0.6 pad 1.52)
  Top 0.406: v82.23,205.74 arc45 81.76,204.59 81.76,200.98
  Top 0.813: 81.76,200.87 81.76,200.98
  Top 1.016: IC3.7 88.11,196.23 arc90 85.27,199.07 83.55,199.07 arc-90 81.76,200.87
  Bottom 0.406: COM1.8 81.86,206.79 v82.23,205.74
RS232A3
  Bottom 1.016: IC3.13 COM1.3
RS232A4
  Bottom 0.406: 79.22,200.18 79.22,205.42 79.14,205.5 79.14,210.5 COM1.7
  Bottom 0.61: IC3.8 90.65,196.01 arc90 88.85,197.8 81.01,197.8 arc-90 79.22,199.6 79.22,200.18
RS232B1
  Bottom 0.813: COM2.2 197.33,207.96 IC4.14
RS232B2  (via drill 0.6 pad 1.52)
  Top 0.406: 201.14,200.34 201.14,204.97 arc-45 v201.45,205.74
  Top 1.27: IC4.7 207.49,196.23 arc90 204.65,199.07 202.41,199.07 arc-90 201.14,200.34
  Bottom 0.406: 201.24,206.32 COM2.8
  Bottom 0.813: v201.45,205.74 201.24,206.32
RS232B3
  Bottom 0.813: IC4.13 COM2.3
RS232B4
  Bottom 0.406: COM2.7 198.49,205.52 198.6,205.42 198.6,200.34
  Bottom 0.61: IC4.8 arc90 207.49,197.8 201.14,197.8 arc-90 198.6,200.34
RST
  Top 1.016: 120.07,195.26 IC2.7
  Top 1.27: R1.2 143.99,96.07 arc-45 145.87,100.64 187.88,142.94 arc45 190.02,148.14 190.02,182.94 arc45 187.82,188.26 185.53,190.55 arc-45 183.36,195.79 183.36,198.3 arc90 178.78,202.88 131.38,202.88 arc45 126.89,201.02 121.87,196.01 arc-45 120.07,195.26
  Bottom 1.016: IC2.7 118.59,195.26 arc90 117.32,193.99 117.32,190.18 | 117.32,190.18 117.32,186.9 arc90 119.11,185.1 IC2.3 | 117.32,190.18 IC2.5 | 151.61,92.39 U1.20 | 147.8,94.93 R1.2 | 151.61,92.39 151.61,93.14 arc90 149.81,94.93 147.8,94.93 | 147.8,94.93 C4.1 | RST.1 136.48,92.37 arc-45 138.5,91.53 140.39,89.63 arc45 142.93,88.58 149.81,88.58 arc90 151.61,90.38 151.61,92.39
SCL
  Top 1.016: IC5.6 133.83,68.26 arc-90 135.1,69.53 arc90 137.64,72.07 Z1.C
  Bottom 1.016: Z1.C R33.1 Z1.C | Z1.C S33.1 155.12,79.69 arc-90 157.96,76.85 157.96,66.25 arc-90 156.16,64.45 154.67,64.45 arc-90 152.88,66.25 IC6.6
SDA
  Top 1.016: IC5.5 137.34,66.99 arc90 140.18,69.83 Z2.C
  Bottom 1.016: Z2.C R34.1 Z2.C | Z2.C S33.2 153.62,77.15 arc-90 155.42,75.36 IC6.5
V+
  Bottom 1.016: R151.2 Q18.1 | 79.22,7.3 M.2 | 95.73,7.3 POW.2
  Bottom 1.676: 76.68,17.46 D9.C arc-90 72.87,18.73 R153.2 | 76.68,17.46 R151.2 | M.2 79.24,10.53 arc45 C69.2 76.68,14.92 76.68,17.46 | 79.22,7.3 79.22,7.06 arc90 81.99,4.29 92.71,4.29 arc90 95.73,7.3 JP26.1
VAR1
  Bottom 1.016: S42.13 JP11.1
VAR2
  Bottom 1.016: S42.12 161.77,168.59 arc-90 JP12.1
VBAT1
  Bottom 1.016: B2.+ 158.27,52.07 153.64,56.7 arc-45 152.88,58.55 IC6.3
VCC  (via drill 0.6 pad 1.68)
  Top 1.27: 230.9,35.24 IC8.10 | C53.2 PS1.2 | 323.06,21.27 IC7.10 | 323.06,21.27 C63.1 | D6.C 110.13,31.43 arc45 102.89,28.43 95.79,21.34 arc45 93.19,15.05 v93.19,14.92 | D2.A 81.88,216.85 arc45 76,214.42 74.47,212.89 arc45 72.87,209.01 IC3.16 | Q12.1 235.47,61.86 arc-45 227.81,80.38 v227.81,100.01 | 36.52,197.8 D1.A | 131.55,162.51 131.66,162.61 | IC10.8 20.49,178.75 arc45 23.18,179.87 24.21,180.9 arc-45 28.23,182.56 | IC7.16 320.22,36.51 arc-90 323.06,33.67 323.06,21.27 | 106.84,154.62 107.16,154.62 107.16,152.36
  Top 1.676: Q4.1 Q5.1 Q2.1 Q3.1 | 230.9,35.24 arc-90 233.52,32.62 233.52,22.29 arc-90 231.23,20 IC8.16 226.93,20 arc-45 224.09,21.18 221.67,23.59 arc45 218.46,24.92 207.15,24.92 arc45 201.22,22.47 C68.1 | v345.92,111.44 v337.03,111.44 | IC12.3 338.3,58.4 arc-90 335.46,55.56 v321.79,55.56 | R110.2 v343.38,50.48 | IC6.8 147.8,67.52 arc45 147.27,68.79 146.56,69.5 arc-45 145.26,71.75 145.26,88.58 | 145.26,88.58 C28.1 | v48.74,11.11 v43.66,11.11 | R126.2 235.22,206.69 arc-45 229.61,209.02 R127.2 199.43,216.85 arc90 192.25,209.67 IC4.16 | R101.A 182.09,183.34 arc45 179.94,189.79 arc-45 179.55,191.27 R107.A | D7.C arc-45 130.02,34.5 130.02,48.69 arc45 127.85,53.92 124.29,57.48 arc-45 122.4,62.05 122.4,67.43 arc-45 123.88,71.02 R32.2 | JP6.3 72.87,169.55 arc45 72.49,170.46 70.97,171.98 arc45 66.88,173.67 61.73,173.67 arc-45 56.89,175.68 50.01,182.56 | 50.01,182.56 50.01,183.43 arc45 47.03,190.62 42.2,195.45 arc45 36.52,197.8 | 131.66,162.61 arc45 R111.2 141.45,164.78 | 131.55,162.51 arc45 130.02,158.8 130.02,154.62 | 130.02,154.62 130.02,147.64 arc-90 IC13.3 | IC11.1 178.9,173.67 arc45 175.67,172.33 175.5,172.16 arc-45 171.48,170.5 151.6,170.5 arc45 148.36,169.16 145.16,165.96 arc-45 142.32,164.78 141.45,164.78 | 141.45,164.78 C53.2 | R113.2 100.41,160.97 arc-45 103.25,159.8 104.66,158.39 arc-45 107.16,152.36 D5.C | 145.26,88.58 143.8,88.58 arc-45 139.78,90.25 100.43,129.6 arc-45 97,137.88 97,155.37 arc-45 C44.2 | 50.01,182.56 28.23,182.56 | 107.16,154.62 130.02,154.62
  Bottom 0.61: JP10.2
  Bottom 1.016: C53.2 arc90 137.64,173.67 C52.1 | R111.2 C42.2 | IC11.1 180.82,173.67 | 66.04,195.9 66.04,193.99 JP10.2 | SPK.1 63.98,4.76 C51.2 | 156.69,4.76 PWR3.1 | 190.98,8.05 R149.2 | 352.27,111.44 PWR4.1 | 348.46,111.42 348.46,111.44 | 13.08,135.48 13.33,135.73 | 11.91,102.55 11.88,102.58 | 156.66,1.77 156.69,1.75 | v227.81,100.01 217.65,100.01 arc-90 SW2.2 | 66.04,195.9 | C16.2 67.95,197.8 arc90 66.04,195.9
  Bottom 1.27: IC3.16 72.87,202.14 arc-90 71.07,200.34 C15.1 C16.2 | C29.2 314.17,37.78 arc90 315.44,36.51 IC7.16 317.21,36.51 arc90 321.79,41.09 321.79,51.75 | U1.52 C3.1 174.47,135.87 arc-90 171.63,133.03 146.53,133.03 arc-90 143.99,135.57 C2.1 | C1.1 R1.1 U1.21 C28.1 | IC10.8 20.27,178.75 arc90 22.07,180.55 22.07,182.78 arc90 18.47,186.37 16.99,186.37 | 16.99,186.37 C33.1 | R107.A 179.55,198.85 arc-90 175.95,195.26 169.69,195.26 arc-90 166.85,198.1 R100.A 171.12,203.34 arc45 173.22,208.42 PWR2.1 | R127.2 arc90 222.16,216.46 | LED19.A 22.7,63.18 arc-90 R125.2 | C26.2 145.26,64.45 | C55.2 C56.1 | R123.2 15.72,13.65 Q14.1 | 310.99,192.09 310.99,185.49 arc90 315.83,180.66 U$1.VCC | 310.99,192.09 U$1.SW1 | TR2.4 C63.1 C65.1 330.68,20.96 arc-90 336.06,26.35 C62.1 | K1.1 D6.C | 142.72,1.75 LED22.A | JP5.1 arc90 156.69,10.8 156.69,4.76 | 231.09,35.24 arc90 232.89,37.04 C30.2 | Q3.1 303.89,201.61 arc-90 310.99,194.51 310.99,192.09 | 143.99,142.81 U1.64 | 127.48,1.75 LED21.A | 16.99,186.37 C34.2 | 111.6,13.65 111.6,14.09 | C41.1 343.88,63.18
  Bottom 1.676: C20.1 C21.2 | C20.1 190.45,200.34 arc90 192.25,202.14 IC4.16 | U1.64 C2.1 | JP15.1 C50.2 D5.C | D1.A 36.04,201.61 | 36.04,201.61 36.04,202.36 arc-45 36.41,203.25 36.78,203.63 arc45 37.31,204.9 C7.1 C8.1 C9.2 37.31,219.39 | 36.04,201.61 IC1.OUT | 37.31,219.39 LED1.A | 47.47,210.5 C32.2 | 47.47,210.5 C31.1 47.47,219.39 | 47.47,210.5 IC9.8 | 37.31,219.39 47.47,219.39 | C44.2 R113.2 98.27,163.2 arc90 92.88,168.59 JP6.3 | 182.09,173.67 R101.A | 182.09,173.67 arc-90 186.53,169.23 C36.1 | 180.82,173.67 182.09,173.67 | R107.A arc-90 180.82,200.34 C20.1 | 222.16,216.46 PS2.4 | R126.2 C61.1 249.61,202.88 arc-45 251.41,202.14 arc45 252.68,201.61 Q4.1 | 10.95,63.18 LED19.A | 9.37,63.18 10.95,63.18 | 9.37,63.18 LED18.A | R33.2 R34.2 R31.2 R32.2 C25.1 128.75,64.45 | 145.26,64.45 arc90 IC6.8 | 128.75,64.45 IC5.8 | 128.75,64.45 C27.1 C26.2 | 17.62,11.11 R123.2 | 17.62,11.11 17.62,8.32 arc90 19.91,6.03 36.92,6.03 arc90 39.21,8.32 R121.1 C55.2 v43.66,11.11 | RE1.5 v343.38,50.48 C64.1 | 343.38,61.91 R110.2 arc45 346.44,58.1 R140.1 | 343.38,61.91 C41.1 | IC12.3 343.38,61.91 | D7.C K2.1 arc-90 128.75,26.35 116.05,26.35 | 116.05,26.35 K1.1 | PWR3.1 156.66,1.77 155.42,1.75 142.72,1.75 127.48,1.75 111.6,1.75 | 231.09,35.24 IC8.10 227.75,35.24 arc-90 224.47,38.52 arc-45 226.1,42.45 228.21,44.56 arc-45 Q12.1 Q13.1 Q6.1 Q11.1 Q10.1 Q7.1 Q9.1 Q8.1 321.79,51.75 v321.79,55.56 | JP8.3 arc-90 198.91,22.22 C68.1 198.91,19.09 arc-45 198.44,17.94 197.74,17.24 arc45 197.33,16.24 197.33,12.68 arc-90 194.49,9.84 OK1.8 192.77,9.84 arc90 190.98,8.05 190.98,4.76 arc-90 187.96,1.75 156.69,1.75 | 356.08,111.44 356.08,149.54 arc90 C.1
  Bottom 1.676: 356.08,111.44 352.27,111.44 | 356.08,111.44 356.08,77.4 arc-90 352.66,73.98 JP2.1 348.46,67.76 arc-90 343.88,63.18 | v337.03,111.44 332.15,111.44 arc-90 328.14,115.46 SW3.2 | PWR4.1 348.46,111.42 | JP4.1 348.46,111.44 v345.92,111.44 | JP1.1 14.45,138.42 arc-45 13.33,135.73 | 13.08,135.48 arc45 11.91,132.64 11.91,102.55 12.91,101.55 arc-45 14.45,97.84 JP3.1 14.45,94.06 arc-45 13.27,91.22 11.69,89.63 arc45 10.95,87.09 10.95,63.18 | 11.88,102.58 PWR1.1 | IC13.3 141.7,145.1 arc-90 143.99,142.81 | v93.19,14.92 JP26.2 | 63.98,1.75 C51.2 | 111.6,1.75 63.98,1.75 | 63.98,1.75 53.6,1.75 arc-90 48.74,6.61 v48.74,11.11 | 9.37,63.18 9.37,55.78 arc-45 8.31,53.24 6.9,51.82 arc45 5.56,48.59 5.56,15.69 arc90 10.14,11.11 17.62,11.11 | 111.6,1.75 111.6,13.65 111.6,21.91 arc-90 116.05,26.35 | 47.47,219.39 93.25,219.39 arc-45 96.12,218.2 D2.A
VPROG
  Top 1.016: R6.2 130.65,181.91 arc-45 129.77,179.78 122.8,172.81 arc-45 118.76,171.13 114.65,171.13 arc-90 112.24,173.55 IC2.20 113.06,180.02 arc90 114.78,181.74 114.78,202.26 arc45 113.44,205.49 109.26,209.67 arc-45 108.43,211.68 R4.2
  Bottom 1.016: R6.2 R5.2 | C11.1 C10.2 IC2.20 | R4.2 D2.C 104.24,216.48 arc45 LED2.A
WP
  Bottom 1.016: S33.3 R31.1 134.13,74.61 arc90 131.29,71.77 IC5.7

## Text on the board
Bottom: eng.walid@al-awail.com
WEDO: 5 | G | PS2 | B | A | RS232B | RS232A | DC | 6~12V | DISPLAY | TXD | CTS | RXD | RTS | RS485 | ADC3 | ADC4 | TX | DE | RX | LR | Q | PRE | RX | TX | ADC | CTS | LEDs | PORTF | G | DAC | G | 5 | NTC | LDR | LM35 | INT4 | Vref | G | INT5 | 0 | 7 | DAC-SW | IN | HUM | Q | INT6 | 0 | 5 | G | 5 | INT7 | 0 | PORTE | ON | PORTA | 7 | G | 5 | GLCD | G | 7 | 5 | LCD | ON | G | DC | DC | 5 | 7 | 1 | 2 | 3 | A | G | 5 | RST | 0 | PORTB | 4 | 5 | 6 | B | PORTC | SCL | SDA | 0 | WP | G | 5 | SQW | DS1820 | 7 | 8 | 9 | C | 7 | MMC | IN | LOCK | MATRIX DSP | INT3 | 0 | D | * | # | INT2 | INT1 | REL1 | REL2 | INT0 | LEDs | PWM | SPK | 5 | G | RC | 0 | 7 | D | T1 | ON | G | A | ASK RECEIVER | QR1 | QR2 | DC | 5 | SPK | ICP | + | _ | + | _ | IR-RX | + | G | 5 | E | ASK TX | PORTD | IR-TX | IR-TX | DESIGNED BY: Eng. WALID BALID | 2008 | MOTOR | EX.VM | AC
